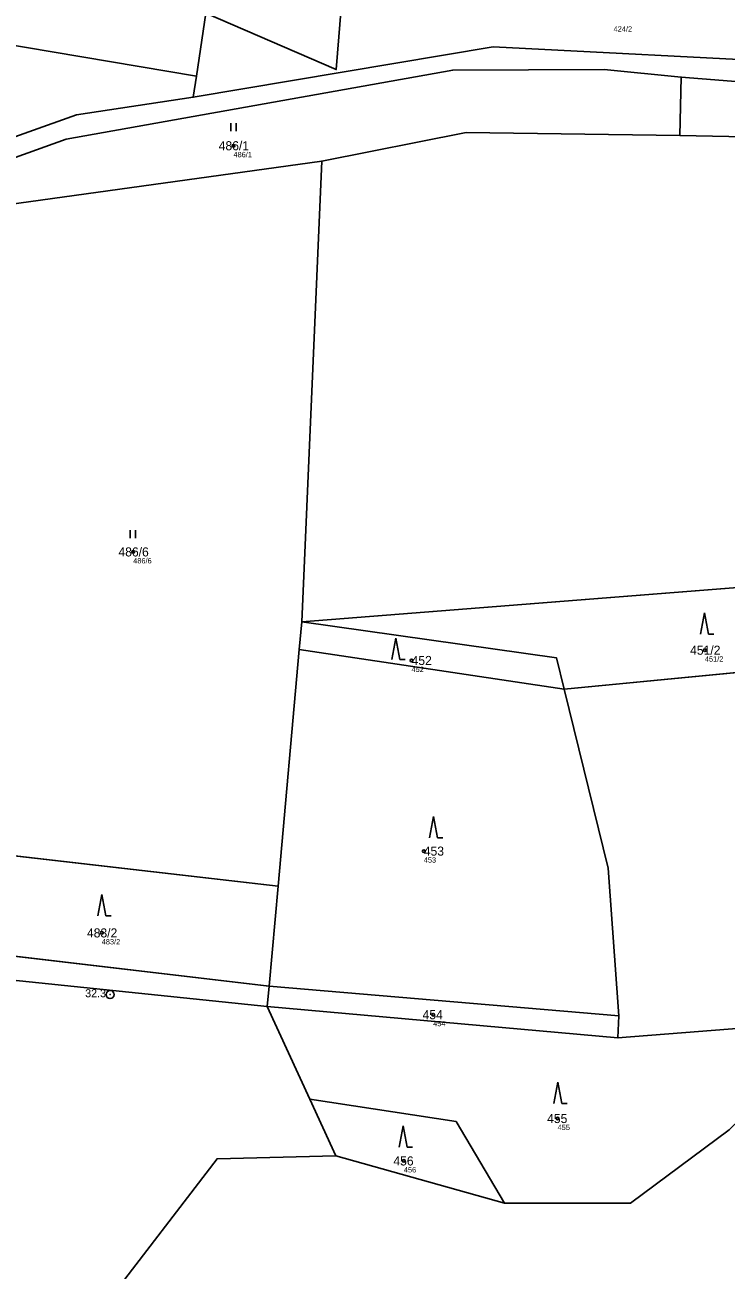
# Model space of a CAD drawing. Extents: x -767985 to -763816, y -1059600 to -1057360.
# Drawn here: x -764898.8 to -764767.3, y -1058190.5 to -1057957.1 of the extents above; entities that cross this region are included whole.
import ezdxf

# ---------------------------------------------------------------- set-up
doc = ezdxf.new("R2010")
doc.units = 0
for name, color, linetype in [('Definiční body', 7, 'Continuous'), ('Hranice parcel', 7, 'Continuous'), ('Parcelní čísla', 7, 'Continuous'), ('Polygon parcely', 7, 'Continuous'), ('Značky bodu BP', 7, 'Continuous'), ('Značky kultur', 7, 'Continuous')]:
    doc.layers.add(name, color=color, linetype=linetype)

msp = doc.modelspace()

# ---------------------------------------------------------------- linework, layer by layer
at = {"layer": 'Definiční body'}
for centre in [(-764859.67, -1057979.78994), (-764878.46, -1058055.91994), (-764771.31, -1058074.33994), (-764826.29, -1058076.26994), (-764824, -1058111.99994), (-764884.36, -1058127.32994), (-764822.25, -1058142.65994), (-764798.91, -1058162.11994), (-764827.73, -1058170.06994)]:
    msp.add_circle(centre, 0.25, dxfattribs=at)
at = {"layer": 'Hranice parcel'}
for p, q in [((-764864.88, -1057954.96), (-764866.61, -1057966.77)), ((-764867.2, -1057970.69), (-764866.61, -1057966.77)), ((-764775.73, -1057966.92), (-764775.99, -1057977.9)), ((-764843.12, -1057982.67), (-764846.86, -1058069.03)), ((-764735.02, -1058060.23), (-764846.86, -1058069.03)), ((-764846.86, -1058069.03), (-764847.34, -1058074.2)), ((-764847.34, -1058074.2), (-764851.32, -1058118.57)), ((-764847.34, -1058074.2), (-764797.69, -1058081.64)), ((-764797.69, -1058081.64), (-764734.36, -1058075.5)), ((-764851.32, -1058118.57), (-764915.34, -1058111.21)), ((-764851.32, -1058118.57), (-764853.01, -1058137.34)), ((-764917.17, -1058129.74), (-764853.01, -1058137.34)), ((-764853.01, -1058137.34), (-764853.35, -1058141.1)), ((-764853.01, -1058137.34), (-764787.43, -1058142.88)), ((-764787.61, -1058147.02), (-764853.35, -1058141.1)), ((-764853.35, -1058141.1), (-764845.36, -1058158.49)), ((-764787.43, -1058142.88), (-764787.61, -1058147.02)), ((-764845.36, -1058158.49), (-764840.47, -1058169.12)), ((-764808.85, -1058177.98), (-764840.47, -1058169.12))]:
    msp.add_line(p, q, dxfattribs=at)
for points in [[(-764830.95, -1057939.9), (-764839.22, -1057950.88), (-764840.4, -1057965.52), (-764864.88, -1057954.96)], [(-764866.61, -1057966.77), (-764909.62, -1057959.5), (-764922.72, -1057962.17), (-764932.81, -1057959.94)], [(-764867.2, -1057970.69), (-764810.99, -1057961.28), (-764752.85, -1057964.23), (-764670.44, -1057986.77)], [(-764775.73, -1057966.92), (-764790.22, -1057965.47), (-764818.58, -1057965.6), (-764891.01, -1057978.57), (-764941.35, -1057996.59), (-764953.08, -1058003.41)], [(-764667.83, -1057992.4), (-764692.55, -1057983.97), (-764752.96, -1057968.74), (-764775.73, -1057966.92)], [(-764941.9, -1057992.83), (-764889.08, -1057974.01), (-764867.2, -1057970.69)], [(-764843.12, -1057982.67), (-764816.05, -1057977.34), (-764775.99, -1057977.9)], [(-764775.99, -1057977.9), (-764754.5, -1057978.28), (-764667.92, -1057994.92)], [(-764902.47, -1057993.57), (-764902.14, -1057990.88), (-764843.12, -1057982.67)], [(-764846.86, -1058069.03), (-764799.14, -1058075.76), (-764797.69, -1058081.64)], [(-764787.43, -1058142.88), (-764789.41, -1058115.18), (-764797.69, -1058081.64)], [(-764853.35, -1058141.1), (-764952.86, -1058130.8), (-764973.5, -1058131.38), (-765007.32, -1058141.15)], [(-764808.85, -1058177.98), (-764785.26, -1058177.98), (-764766.77, -1058164.23), (-764755.73, -1058153.52), (-764757.4, -1058144.64), (-764787.61, -1058147.02)], [(-764845.36, -1058158.49), (-764817.95, -1058162.69), (-764808.85, -1058177.98)], [(-764840.47, -1058169.12), (-764862.75, -1058169.65), (-764883.53, -1058196.78), (-764904.39, -1058195.29), (-764932.67, -1058172.94), (-764971.18, -1058173.26), (-764992.45, -1058178.62)]]:
    msp.add_lwpolyline(points, dxfattribs=at)
at = {"layer": 'Polygon parcely'}
for points in [[(-764824.52, -1057888.95), (-764847.74, -1057890.35), (-764865.15, -1057904.18), (-764866.53, -1057915.08), (-764907.86, -1057913.54), (-764906.75, -1057916.38), (-764892.72, -1057930.84), (-764883.34, -1057930.84), (-764861.5, -1057932.66), (-764864.88, -1057954.96), (-764840.4, -1057965.52), (-764839.22, -1057950.88), (-764830.95, -1057939.9), (-764813.3, -1057912.55)], [(-764861.5, -1057932.66), (-764883.34, -1057930.84), (-764892.72, -1057930.84), (-764932.17, -1057930.84), (-764991.8, -1057932.26), (-765014.74, -1057935.4), (-765037.75, -1057945.96), (-765035.06, -1057971.04), (-765033.12, -1057970.76), (-764966.89, -1057961.61), (-764945.36, -1057957.17), (-764932.81, -1057959.94), (-764922.72, -1057962.17), (-764909.62, -1057959.5), (-764866.61, -1057966.77), (-764864.88, -1057954.96)], [(-764810.99, -1057961.28), (-764752.85, -1057964.23), (-764670.44, -1057986.77), (-764727.9, -1057957.13), (-764732.83, -1057955.96), (-764775.4, -1057945.74), (-764830.95, -1057939.9), (-764839.22, -1057950.88), (-764840.4, -1057965.52), (-764864.88, -1057954.96), (-764866.61, -1057966.77), (-764867.2, -1057970.69)], [(-764889.08, -1057974.01), (-764867.2, -1057970.69), (-764866.61, -1057966.77), (-764909.62, -1057959.5), (-764922.72, -1057962.17), (-764932.81, -1057959.94), (-764931.99, -1057984.76), (-764943.4, -1057989.54), (-764941.9, -1057992.83)], [(-764941.35, -1057996.59), (-764953.08, -1058003.41), (-764923.74, -1057993.97), (-764902.47, -1057993.57), (-764902.14, -1057990.88), (-764843.12, -1057982.67), (-764816.05, -1057977.34), (-764775.99, -1057977.9), (-764775.73, -1057966.92), (-764790.22, -1057965.47), (-764818.58, -1057965.6), (-764891.01, -1057978.57)], [(-764752.96, -1057968.74), (-764775.73, -1057966.92), (-764775.99, -1057977.9), (-764754.5, -1057978.28), (-764667.92, -1057994.92), (-764667.83, -1057992.4), (-764692.55, -1057983.97)], [(-764846.86, -1058069.03), (-764735.02, -1058060.23), (-764667.35, -1058054.9), (-764666.06, -1058048.83), (-764668.76, -1058025.15), (-764667.92, -1057994.92), (-764754.5, -1057978.28), (-764775.99, -1057977.9), (-764816.05, -1057977.34), (-764843.12, -1057982.67)], [(-764847.34, -1058074.2), (-764846.86, -1058069.03), (-764843.12, -1057982.67), (-764902.14, -1057990.88), (-764902.47, -1057993.57), (-764915.34, -1058111.21), (-764851.32, -1058118.57)], [(-764846.86, -1058069.03), (-764799.14, -1058075.76), (-764797.69, -1058081.64), (-764734.36, -1058075.5), (-764735.02, -1058060.23)], [(-764847.34, -1058074.2), (-764797.69, -1058081.64), (-764799.14, -1058075.76), (-764846.86, -1058069.03)], [(-764853.01, -1058137.34), (-764787.43, -1058142.88), (-764789.41, -1058115.18), (-764797.69, -1058081.64), (-764847.34, -1058074.2), (-764851.32, -1058118.57)], [(-764851.32, -1058118.57), (-764915.34, -1058111.21), (-764916.16, -1058119.5), (-764917.17, -1058129.74), (-764853.01, -1058137.34)], [(-765007.32, -1058141.15), (-764973.5, -1058131.38), (-764952.86, -1058130.8), (-764853.35, -1058141.1), (-764853.01, -1058137.34), (-764917.17, -1058129.74), (-764949.93, -1058126.62), (-764973.79, -1058127.56), (-764986.83, -1058130.44)], [(-765007.32, -1058141.15), (-765026.78, -1058154.83), (-765024.67, -1058160.41), (-764992.45, -1058178.62), (-764971.18, -1058173.26), (-764932.67, -1058172.94), (-764904.39, -1058195.29), (-764883.53, -1058196.78), (-764862.75, -1058169.65), (-764840.47, -1058169.12), (-764845.36, -1058158.49), (-764853.35, -1058141.1), (-764952.86, -1058130.8), (-764973.5, -1058131.38)], [(-764853.35, -1058141.1), (-764787.61, -1058147.02), (-764787.43, -1058142.88), (-764853.01, -1058137.34)], [(-764808.85, -1058177.98), (-764785.26, -1058177.98), (-764766.77, -1058164.23), (-764755.73, -1058153.52), (-764757.4, -1058144.64), (-764787.61, -1058147.02), (-764853.35, -1058141.1), (-764845.36, -1058158.49), (-764817.95, -1058162.69)], [(-764845.36, -1058158.49), (-764840.47, -1058169.12), (-764808.85, -1058177.98), (-764817.95, -1058162.69)]]:
    msp.add_lwpolyline(points, close=True, dxfattribs=at)
for points in [[(-764752.85, -1057964.23), (-764810.99, -1057961.28), (-764867.2, -1057970.69), (-764889.08, -1057974.01), (-764941.9, -1057992.83), (-764977.9, -1058013.16), (-764997.81, -1058026.98), (-765014.47, -1058041.4), (-765036.03, -1058062.77), (-765105.8, -1058124.37), (-765152.28, -1058167.42), (-765170.88, -1058193.05)], [(-765168.45, -1058197.39), (-765147.71, -1058168.31), (-765119.64, -1058141.6), (-765063.83, -1058093.47), (-765028.09, -1058061.61), (-765006.03, -1058039.5), (-764991.99, -1058028.08), (-764977.18, -1058017.42), (-764953.08, -1058003.41), (-764941.35, -1057996.59), (-764891.01, -1057978.57), (-764818.58, -1057965.6), (-764790.22, -1057965.47), (-764775.73, -1057966.92), (-764752.96, -1057968.74)], [(-764734.36, -1058075.5), (-764797.69, -1058081.64), (-764789.41, -1058115.18), (-764787.43, -1058142.88), (-764787.61, -1058147.02), (-764757.4, -1058144.64)], [(-764766.77, -1058164.23), (-764785.26, -1058177.98), (-764808.85, -1058177.98), (-764840.47, -1058169.12), (-764862.75, -1058169.65), (-764883.53, -1058196.78)]]:
    msp.add_lwpolyline(points, dxfattribs=at)
at = {"layer": 'Značky bodu BP'}
for radius in [0.75, 0.03]:
    msp.add_circle((-764882.79, -1058138.88982), radius, dxfattribs=at)
at = {"layer": 'Značky kultur'}
for p, q in [((-764860.181, -1057977.09), (-764860.181, -1057975.59)), ((-764859.18, -1057977.09), (-764859.18, -1057975.59)), ((-764879.021, -1058053.36), (-764879.021, -1058051.86)), ((-764878.02, -1058053.36), (-764878.02, -1058051.86)), ((-764771.41, -1058067.34), (-764772.16, -1058071.34)), ((-764770.66, -1058071.34), (-764771.41, -1058067.34)), ((-764829.21, -1058072.06), (-764829.96, -1058076.06)), ((-764828.46, -1058076.06), (-764829.21, -1058072.06)), ((-764770.66, -1058071.34), (-764769.664, -1058071.34)), ((-764828.46, -1058076.06), (-764827.464, -1058076.06)), ((-764822.2, -1058105.5), (-764822.95, -1058109.5)), ((-764821.45, -1058109.5), (-764822.2, -1058105.5)), ((-764821.45, -1058109.5), (-764820.454, -1058109.5)), ((-764884.37, -1058120.14), (-764885.12, -1058124.14)), ((-764883.62, -1058124.14), (-764884.37, -1058120.14)), ((-764883.62, -1058124.14), (-764882.624, -1058124.14)), ((-764798.87, -1058155.29), (-764799.62, -1058159.29)), ((-764798.12, -1058159.29), (-764798.87, -1058155.29)), ((-764798.12, -1058159.29), (-764797.124, -1058159.29)), ((-764827.86, -1058163.49), (-764828.61, -1058167.49)), ((-764827.11, -1058167.49), (-764827.86, -1058163.49)), ((-764827.11, -1058167.49), (-764826.114, -1058167.49))]:
    msp.add_line(p, q, dxfattribs=at)

# ---------------------------------------------------------------- texts
at = {"layer": 'Definiční body'}
for s, p in [('424/2', (-764788.41, -1057958.396)), ('486/1', (-764859.67, -1057981.946)), ('486/6', (-764878.46, -1058058.076)), ('451/2', (-764771.31, -1058076.496)), ('452', (-764826.29, -1058078.426)), ('453', (-764824, -1058114.156)), ('483/2', (-764884.36, -1058129.486)), ('454', (-764822.25, -1058144.816)), ('455', (-764798.91, -1058164.276)), ('456', (-764827.73, -1058172.226))]:
    msp.add_text(s, height=0.999996, dxfattribs=at).set_placement(p)
at = {"layer": 'Parcelní čísla'}
for s, p in [('486/1', (-764862.443, -1057980.64)), ('486/6', (-764881.233, -1058056.77)), ('451/2', (-764774.083, -1058075.19)), ('452', (-764826.29, -1058077.12)), ('453', (-764824, -1058112.85)), ('483/2', (-764887.133, -1058128.18)), ('454', (-764824.224, -1058143.51)), ('455', (-764800.884, -1058162.97)), ('456', (-764829.704, -1058170.92))]:
    msp.add_text(s, height=1.699998, dxfattribs=at).set_placement(p)
at = {"layer": 'Značky bodu BP'}
msp.add_text('32.3', height=1.499994, dxfattribs=at).set_placement((-764887.465, -1058139.389))

doc.saveas('drawing.dxf')
